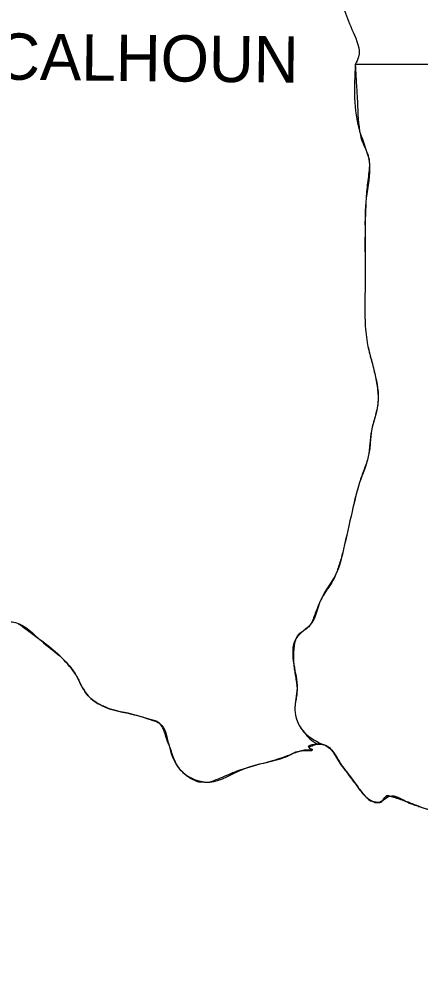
# Model space of a CAD drawing. Extents: x 3046 to 131673, y -8885 to 10756.
# Drawn here: x 104255 to 104619, y 5299 to 6157 of the extents above; entities that cross this region are included whole.
import ezdxf

# ---------------------------------------------------------------- set-up
doc = ezdxf.new("R2010")
doc.units = 0
for name, color, linetype in [('1', 7, 'Continuous'), ('2', 7, 'Continuous'), ('R_Annotation', 7, 'Continuous')]:
    doc.layers.add(name, color=color, linetype=linetype)

msp = doc.modelspace()

# ---------------------------------------------------------------- linework, layer by layer
at = {"layer": '1'}
msp.add_lwpolyline([(104560.45471461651, 6115.623024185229), (105002.69459609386, 6116.601431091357)], dxfattribs=at)
msp.add_lwpolyline([(104560.45471461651, 6115.623024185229), (105002.69459609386, 6116.601431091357)], dxfattribs=at)
for points in [[(104381.40626708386, 6507.964157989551), (104403.90962378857, 6493.2880556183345), (104422.49935344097, 6473.719919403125), (104436.19704890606, 6459.0438170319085), (104445.00271018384, 6442.410901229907), (104456.7435920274, 6422.842764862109), (104473.3765078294, 6385.663305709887), (104488.05261020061, 6372.944017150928), (104508.59915332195, 6360.22472843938), (104521.31844207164, 6351.419067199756), (104534.03773059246, 6323.04526951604), (104539.90817149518, 6294.671471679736), (104550.67064643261, 6269.23289463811), (104555.56268058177, 6249.664758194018), (104546.75701915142, 6230.096621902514), (104544.8002055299, 6190.960349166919), (104550.67064643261, 6164.543365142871), (104558.49790099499, 6144.975228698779), (104563.3899351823, 6122.471871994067), (104560.45471461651, 6115.623024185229)], [(104381.40626708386, 6507.964157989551), (104403.90962378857, 6493.2880556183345), (104422.49935344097, 6473.719919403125), (104436.19704890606, 6459.0438170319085), (104445.00271018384, 6442.410901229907), (104456.7435920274, 6422.842764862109), (104473.3765078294, 6385.663305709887), (104488.05261020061, 6372.944017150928), (104508.59915332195, 6360.22472843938), (104521.31844207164, 6351.419067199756), (104534.03773059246, 6323.04526951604), (104539.90817149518, 6294.671471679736), (104550.67064643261, 6269.23289463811), (104555.56268058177, 6249.664758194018), (104546.75701915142, 6230.096621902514), (104544.8002055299, 6190.960349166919), (104550.67064643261, 6164.543365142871), (104558.49790099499, 6144.975228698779), (104563.3899351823, 6122.471871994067), (104560.45471461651, 6115.623024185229)], [(104560.45471461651, 6115.623024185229), (104564.3683418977, 6054.961801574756), (104573.17400332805, 6025.609597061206), (104570.23878280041, 5994.300578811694), (104569.26037604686, 5963.9699675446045), (104569.26037604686, 5936.574576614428), (104569.26037604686, 5910.157592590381), (104569.26037604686, 5882.7622016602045), (104571.21718970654, 5863.194065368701), (104578.06603736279, 5834.820267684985), (104581.00125792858, 5808.403283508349), (104575.13081698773, 5782.9647063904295), (104572.19559642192, 5759.4829427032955), (104564.3683418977, 5736.0011790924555), (104557.51949424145, 5709.584195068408), (104549.69223971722, 5675.339956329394), (104542.84339187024, 5652.836599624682), (104529.14569659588, 5629.354835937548), (104520.34003516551, 5607.829885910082), (104506.64233970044, 5594.132190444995), (104504.68552604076, 5570.650426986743), (104507.62074660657, 5549.125477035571), (104505.66393294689, 5529.557340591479), (104512.512780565, 5510.967610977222), (104530.12410331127, 5498.2483224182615)], [(104560.45471461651, 6115.623024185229), (104564.3683418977, 6054.961801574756), (104573.17400332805, 6025.609597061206), (104570.23878280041, 5994.300578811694), (104569.26037604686, 5963.9699675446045), (104569.26037604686, 5936.574576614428), (104569.26037604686, 5910.157592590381), (104569.26037604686, 5882.7622016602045), (104571.21718970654, 5863.194065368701), (104578.06603736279, 5834.820267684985), (104581.00125792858, 5808.403283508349), (104575.13081698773, 5782.9647063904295), (104572.19559642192, 5759.4829427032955), (104564.3683418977, 5736.0011790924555), (104557.51949424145, 5709.584195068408), (104549.69223971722, 5675.339956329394), (104542.84339187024, 5652.836599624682), (104529.14569659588, 5629.354835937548), (104520.34003516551, 5607.829885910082), (104506.64233970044, 5594.132190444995), (104504.68552604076, 5570.650426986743), (104507.62074660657, 5549.125477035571), (104505.66393294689, 5529.557340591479), (104512.512780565, 5510.967610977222), (104530.12410331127, 5498.2483224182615)], [(103995.91398108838, 5604.894665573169), (104011.56849017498, 5615.657140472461), (104026.24459235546, 5621.5275813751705), (104040.92069472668, 5618.592361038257), (104056.5752036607, 5616.635547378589), (104070.27289912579, 5618.592361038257), (104087.88422187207, 5615.657140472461), (104102.56032420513, 5606.851479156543), (104119.19324004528, 5600.0026314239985), (104135.82615588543, 5600.0026314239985), (104150.50225825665, 5600.0026314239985), (104163.2215468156, 5591.196970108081), (104186.70331042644, 5592.175376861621), (104206.2714468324, 5600.0026314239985), (104225.83958316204, 5605.873072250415), (104252.25656722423, 5608.80829281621), (104275.73833087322, 5592.175376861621), (104292.37124671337, 5578.477681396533), (104306.06894214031, 5562.823172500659), (104315.85301032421, 5545.2118497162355), (104326.6154852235, 5535.427781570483), (104344.22680796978, 5528.578933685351), (104357.92450343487, 5525.643713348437), (104374.55741946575, 5520.7516791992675), (104383.36308070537, 5516.838051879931), (104391.19033526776, 5498.2483224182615), (104403.90962378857, 5472.809745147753), (104428.36979438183, 5464.004083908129), (104458.70040564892, 5475.744965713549), (104483.16057605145, 5482.593813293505), (104500.77189875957, 5488.46425427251), (104511.53437388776, 5492.377881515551), (104521.31844207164, 5493.356288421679), (104518.38322150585, 5495.313102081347), (104530.12410331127, 5498.2483224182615), (104540.88657824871, 5490.421067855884), (104547.73542605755, 5479.658592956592), (104559.47630790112, 5464.004083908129), (104570.23878280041, 5450.306388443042), (104581.00125792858, 5445.414354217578), (104591.76373282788, 5451.2847951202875), (104606.43983500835, 5446.392761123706), (104619.15912375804, 5441.500726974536), (104633.83522593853, 5437.587099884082), (104646.55451465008, 5436.608692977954), (104663.18743045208, 5432.695065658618), (104675.90671904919, 5425.846218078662), (104687.64760089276, 5418.99737019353), (104699.38848269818, 5406.27808163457), (104711.12936450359, 5386.7099453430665), (104715.04299178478, 5371.05543621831), (104728.74068724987, 5355.400927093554), (104741.45997596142, 5355.400927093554), (104760.0497054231, 5329.962349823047), (104766.89855307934, 5320.178281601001), (104781.57465545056, 5302.56695889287), (104792.33713034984, 5302.56695889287), (104812.88367347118, 5298.653331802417)], [(103995.91398108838, 5604.894665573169), (104011.56849017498, 5615.657140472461), (104026.24459235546, 5621.5275813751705), (104040.92069472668, 5618.592361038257), (104056.5752036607, 5616.635547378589), (104070.27289912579, 5618.592361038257), (104087.88422187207, 5615.657140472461), (104102.56032420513, 5606.851479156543), (104119.19324004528, 5600.0026314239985), (104135.82615588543, 5600.0026314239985), (104150.50225825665, 5600.0026314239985), (104163.2215468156, 5591.196970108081), (104186.70331042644, 5592.175376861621), (104206.2714468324, 5600.0026314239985), (104225.83958316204, 5605.873072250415), (104252.25656722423, 5608.80829281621), (104275.73833087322, 5592.175376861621), (104292.37124671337, 5578.477681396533), (104306.06894214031, 5562.823172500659), (104315.85301032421, 5545.2118497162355), (104326.6154852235, 5535.427781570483), (104344.22680796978, 5528.578933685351), (104357.92450343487, 5525.643713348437), (104374.55741946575, 5520.7516791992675), (104383.36308070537, 5516.838051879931), (104391.19033526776, 5498.2483224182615), (104403.90962378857, 5472.809745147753), (104428.36979438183, 5464.004083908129), (104458.70040564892, 5475.744965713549), (104483.16057605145, 5482.593813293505), (104500.77189875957, 5488.46425427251), (104511.53437388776, 5492.377881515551), (104521.31844207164, 5493.356288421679), (104518.38322150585, 5495.313102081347), (104530.12410331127, 5498.2483224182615), (104540.88657824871, 5490.421067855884), (104547.73542605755, 5479.658592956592), (104559.47630790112, 5464.004083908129), (104570.23878280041, 5450.306388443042), (104581.00125792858, 5445.414354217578), (104591.76373282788, 5451.2847951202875), (104606.43983500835, 5446.392761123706), (104619.15912375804, 5441.500726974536), (104633.83522593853, 5437.587099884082), (104646.55451465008, 5436.608692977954), (104663.18743045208, 5432.695065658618), (104675.90671904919, 5425.846218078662), (104687.64760089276, 5418.99737019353), (104699.38848269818, 5406.27808163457), (104711.12936450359, 5386.7099453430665), (104715.04299178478, 5371.05543621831), (104728.74068724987, 5355.400927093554), (104741.45997596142, 5355.400927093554), (104760.0497054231, 5329.962349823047), (104766.89855307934, 5320.178281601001), (104781.57465545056, 5302.56695889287), (104792.33713034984, 5302.56695889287), (104812.88367347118, 5298.653331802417)]]:
    msp.add_spline(points, degree=3, dxfattribs=at)
at = {"layer": 'R_Annotation'}
for p, q in [((104560.45471461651, 6115.623024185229), (105002.69459609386, 6116.601431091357)), ((105002.69459609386, 6116.601431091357), (104560.45471461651, 6115.623024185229)), ((104530.12410331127, 5498.2483224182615), (104526.4489948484, 5498.289598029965)), ((104547.73542605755, 5479.658592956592), (104540.88657824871, 5490.421067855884))]:
    msp.add_line(p, q, dxfattribs=at)
msp.add_lwpolyline([(104255.4074246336, 5607.249735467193), (104255.19178771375, 5606.851479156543)], dxfattribs=at)
for points in [[(104381.40626708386, 6507.964157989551), (104403.90962378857, 6493.2880556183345), (104422.49935344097, 6473.719919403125), (104436.19704890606, 6459.0438170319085), (104445.00271018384, 6442.410901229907), (104456.7435920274, 6422.842764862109), (104473.3765078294, 6385.663305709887), (104488.05261020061, 6372.944017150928), (104508.59915332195, 6360.22472843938), (104521.31844207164, 6351.419067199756), (104534.03773059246, 6323.04526951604), (104539.90817149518, 6294.671471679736), (104550.67064643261, 6269.23289463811), (104555.56268058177, 6249.664758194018), (104546.75701915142, 6230.096621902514), (104544.8002055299, 6190.960349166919), (104550.67064643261, 6164.543365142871), (104558.49790099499, 6144.975228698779), (104563.3899351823, 6122.471871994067), (104560.45471461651, 6115.623024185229)], [(104560.45471461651, 6115.623024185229), (104561.19388574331, 6100.442878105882), (104562.12875941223, 6085.272435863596), (104564.3683418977, 6054.961801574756), (104566.09778300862, 6047.506277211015), (104569.11470701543, 6040.269379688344), (104571.95986382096, 6033.040641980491), (104572.86201386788, 6029.363562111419), (104573.17400332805, 6025.609597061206), (104572.71926096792, 6017.802566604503), (104571.80683776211, 6009.983006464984), (104570.84419220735, 6002.149487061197), (104570.23878280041, 5994.300578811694), (104569.26037604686, 5963.9699675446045), (104569.26037604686, 5936.574576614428), (104569.26037604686, 5910.157592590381), (104569.26037604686, 5882.7622016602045), (104571.21718970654, 5863.194065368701), (104572.67024739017, 5856.039996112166), (104574.49804366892, 5848.981959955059), (104576.39762488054, 5841.936527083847), (104578.06603736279, 5834.820267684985), (104580.44265025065, 5821.609462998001), (104581.06948304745, 5814.979980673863), (104581.00125792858, 5808.403283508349), (104580.00674081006, 5802.018150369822), (104578.34713408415, 5795.673361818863), (104576.54697904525, 5789.333889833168), (104575.13081698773, 5782.9647063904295), (104574.404179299, 5777.112145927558), (104573.89965654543, 5771.198381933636), (104573.27690887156, 5765.2973392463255), (104572.19559642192, 5759.4829427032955), (104570.43560405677, 5753.5530819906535), (104568.33949226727, 5747.723663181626), (104566.21461892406, 5741.903443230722), (104564.3683418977, 5736.0011790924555), (104557.51949424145, 5709.584195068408), (104549.69223971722, 5675.339956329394), (104546.6660663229, 5663.976363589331), (104544.87054264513, 5658.373878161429), (104542.84339187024, 5652.836599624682), (104539.8823376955, 5646.7152885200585), (104536.29491526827, 5640.914473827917), (104532.55730732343, 5635.204281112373), (104529.14569659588, 5629.354835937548), (104526.75553261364, 5624.073451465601), (104524.6814900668, 5618.606663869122), (104522.63813542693, 5613.13272479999), (104520.34003516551, 5607.829885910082), (104517.32033895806, 5604.171180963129), (104513.24558514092, 5601.228112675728), (104509.29363246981, 5598.161507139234), (104507.73178742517, 5596.319636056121), (104506.64233970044, 5594.132190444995), (104504.46335689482, 5582.396452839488), (104504.68552604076, 5570.650426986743), (104505.31580336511, 5565.269331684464), (104506.20079319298, 5559.88877590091), (104507.06195458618, 5554.50780817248), (104507.62074660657, 5549.125477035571), (104507.42936101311, 5544.243396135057), (104506.66238126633, 5539.349161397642), (104505.88538077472, 5534.451050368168), (104505.66393294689, 5529.557340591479), (104507.42143762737, 5520.087017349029), (104512.512780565, 5510.967610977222), (104515.76936466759, 5506.975695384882), (104519.27863543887, 5503.2002669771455), (104526.4489948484, 5498.289598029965)], [(104418.62406420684, 5463.902332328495), (104411.1065247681, 5467.091752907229), (104407.44932202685, 5469.652617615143), (104403.90962378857, 5472.809745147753), (104395.90943914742, 5485.4049074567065), (104393.67857018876, 5491.804495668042), (104392.53397573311, 5495.02199326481), (104391.19033526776, 5498.2483224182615), (104389.42781863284, 5502.946333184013), (104387.94867833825, 5507.7440876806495), (104386.1335528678, 5512.4413919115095), (104383.36308070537, 5516.838051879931), (104381.4914912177, 5518.438366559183), (104379.2887698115, 5519.434929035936), (104374.55741946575, 5520.7516791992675), (104357.92450343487, 5525.643713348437), (104344.22680796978, 5528.578933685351), (104335.25321235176, 5531.394517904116), (104330.9034153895, 5533.250125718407), (104326.6154852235, 5535.427781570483), (104315.85301032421, 5545.2118497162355), (104313.1786138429, 5549.526623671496), (104310.95866927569, 5554.068424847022), (104308.73987818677, 5558.584769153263), (104306.06894214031, 5562.823172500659), (104292.37124671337, 5578.477681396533), (104275.73833087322, 5592.175376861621), (104255.40742463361, 5607.249735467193)], [(104526.4489948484, 5498.289598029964), (104522.21940416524, 5497.085470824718), (104520.20186393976, 5496.225548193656), (104518.38322150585, 5495.313102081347), (104518.58870250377, 5494.836334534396), (104519.90235285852, 5494.270402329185), (104521.1902426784, 5493.736616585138), (104521.47017429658, 5493.519688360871), (104521.31844207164, 5493.356288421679), (104518.92222562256, 5492.942395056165), (104516.42562731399, 5492.904560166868), (104513.92941933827, 5492.847987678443), (104511.53437388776, 5492.377881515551), (104500.77189875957, 5488.46425427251), (104483.16057605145, 5482.593813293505), (104458.70040564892, 5475.744965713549), (104451.06731356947, 5473.05090158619), (104443.49157289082, 5469.82111527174), (104435.93759577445, 5466.6180337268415), (104428.36979438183, 5464.004083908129), (104418.62406420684, 5463.902332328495)]]:
    msp.add_spline(points, degree=3, dxfattribs=at)
for points, degree in [([(104526.4489948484, 5498.2895980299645), (104527.77603358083, 5498.507009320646), (104529.04028800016, 5498.528174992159), (104530.12410331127, 5498.2483224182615), (104533.80544429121, 5497.297761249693), (104538.16599850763, 5494.106893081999), (104540.88657824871, 5490.421067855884), (104543.49453302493, 5486.8878262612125), (104545.20056692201, 5483.06986031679), (104547.73542605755, 5479.658592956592), (104551.6237224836, 5474.42594767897), (104555.54204939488, 5469.212891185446), (104559.47630790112, 5464.004083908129), (104562.9786819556, 5459.367075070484), (104566.0493375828, 5454.839634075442), (104570.23878280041, 5450.306388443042), (104573.0819560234, 5447.229894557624), (104577.51679466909, 5445.922729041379), (104581.00125792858, 5445.414354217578), (104584.61460166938, 5444.887176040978), (104587.97977203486, 5452.428555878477), (104591.76373282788, 5451.2847951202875), (104596.5386605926, 5449.84149924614), (104601.60180216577, 5448.218975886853), (104606.43983500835, 5446.392761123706), (104610.701699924, 5444.7840327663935), (104614.8697159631, 5443.043456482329), (104619.15912375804, 5441.500726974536), (104623.9399722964, 5439.781245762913), (104628.8524025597, 5438.52568258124), (104633.83522593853, 5437.587099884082), (104638.02018717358, 5436.798805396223), (104642.33978095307, 5437.210001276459), (104646.55451465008, 5436.608692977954), (104652.19992601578, 5435.803272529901), (104657.95340549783, 5435.167223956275), (104663.18743045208, 5432.695065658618), (104667.61243901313, 5430.605025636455), (104671.69378688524, 5428.202973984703), (104675.90671904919, 5425.846218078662), (104679.87073031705, 5423.628710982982), (104683.8117075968, 5421.484634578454), (104687.64760089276, 5418.99737019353), (104692.53254981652, 5415.8298786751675), (104695.85806095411, 5410.993653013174), (104699.38848269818, 5406.27808163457), (104704.04277731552, 5400.061357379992), (104707.8001666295, 5393.541636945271), (104711.12936450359, 5386.7099453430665), (104713.48346290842, 5381.879209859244), (104712.74655418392, 5376.121245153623), (104715.04299178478, 5371.05543621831), (104718.0033169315, 5364.525129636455), (104722.98228923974, 5359.511445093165), (104728.74068724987, 5355.400927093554), (104732.26176662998, 5352.887474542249), (104738.87807919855, 5358.771049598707), (104741.45997596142, 5355.400927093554), (104747.855629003, 5347.0527489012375), (104754.00265373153, 5338.558842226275), (104760.0497054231, 5329.962349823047), (104762.3418786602, 5326.703794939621), (104764.60392083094, 5323.436555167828), (104766.89855307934, 5320.178281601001), (104771.30314960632, 5313.923954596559), (104774.508537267, 5307.179834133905), (104781.57465545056, 5302.56695889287), (104784.8919757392, 5300.401359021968), (104788.81273044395, 5303.231109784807), (104792.33713034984, 5302.56695889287), (104799.18649988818, 5301.276238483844), (104806.03177152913, 5299.9272085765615), (104812.88367347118, 5298.653331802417)], 3), ([(104540.88657824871, 5490.421067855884), (104538.16599850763, 5494.106893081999), (104533.80544429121, 5497.297761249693), (104530.12410331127, 5498.2483224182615)], 2), ([(104559.95373773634, 5463.369277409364), (104559.79539684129, 5463.580658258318), (104559.63630283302, 5463.792256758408), (104559.47630790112, 5464.004083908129), (104555.54204939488, 5469.212891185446), (104551.6237224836, 5474.42594767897), (104547.73542605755, 5479.658592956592)], 3), ([(104570.23878280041, 5450.306388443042), (104566.24071919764, 5454.632547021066), (104563.26156315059, 5458.9534191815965), (104559.95373773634, 5463.369277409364)], 2), ([(104571.47802613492, 5449.149095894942), (104571.03986273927, 5449.503885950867), (104570.62466322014, 5449.888841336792), (104570.23878280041, 5450.306388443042)], 2), ([(104619.15912375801, 5441.500726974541), (104614.86971596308, 5443.043456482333), (104610.701699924, 5444.784032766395), (104606.43983500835, 5446.392761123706), (104601.60180216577, 5448.218975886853), (104596.5386605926, 5449.84149924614), (104591.76373282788, 5451.2847951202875), (104587.97977203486, 5452.428555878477), (104584.61460166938, 5444.887176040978), (104581.00125792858, 5445.414354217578), (104577.98971208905, 5445.853731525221), (104574.26825778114, 5446.889787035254), (104571.47802613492, 5449.149095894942)], 3)]:
    msp.add_open_spline(points, degree=degree, dxfattribs=at)

# ---------------------------------------------------------------- texts
at = {"layer": '2'}
msp.add_text('CALHOUN', height=42.07344995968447, rotation=359.36340559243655, dxfattribs=at).set_placement((104233.66683772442, 6101.925328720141))
msp.add_text('CALHOUN', height=42.07344995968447, rotation=359.36340559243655, dxfattribs=at).set_placement((104233.66683772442, 6101.925328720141))

doc.saveas('drawing.dxf')
